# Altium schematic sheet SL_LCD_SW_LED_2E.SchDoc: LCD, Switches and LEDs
size B; Organization: Altium Limited; Address1: L3, 12a Rodborough Rd; Address2: Frenchs Forest; Address3: NSW; Address4: Australia 2086; DocumentNumber: 3; SheetNumber: 3; SheetTotal: 5; Library Name: SpiritLevel_2E.SchLib
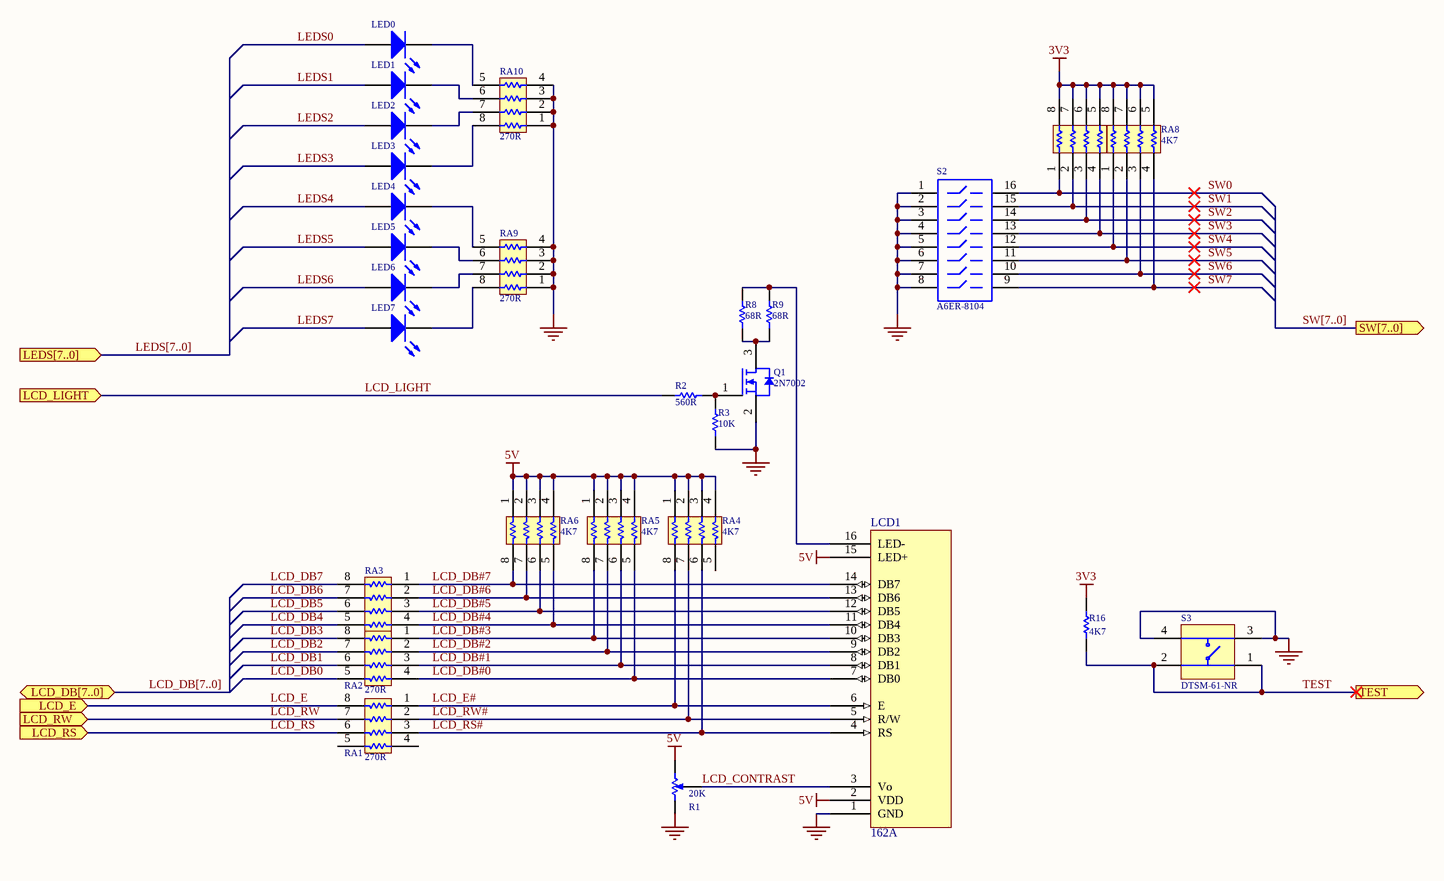
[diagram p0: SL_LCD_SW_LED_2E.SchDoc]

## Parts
LCD1  162A  [162A]
LED0  HSMH-C170  [SMD _LED]  (value not drawn)
LED1  HSMH-C170  [SMD _LED]  (value not drawn)
LED2  HSMH-C170  [SMD _LED]  (value not drawn)
LED3  HSMH-C170  [SMD _LED]  (value not drawn)
LED4  HSMH-C170  [SMD _LED]  (value not drawn)
LED5  HSMH-C170  [SMD _LED]  (value not drawn)
LED6  HSMH-C170  [SMD _LED]  (value not drawn)
LED7  HSMH-C170  [SMD _LED]  (value not drawn)
Q1  2N7002  [SO-G3]
R1  20K  [POT4MM-2]
R2  560R  [CC2012-0805]
R3  10K  [CC2012-0805]
R8  68R  [CC2012-0805]
R9  68R  [CC2012-0805]
R16  4K7  [CC2012-0805]
RA1  270R  [MNR34]
RA2  270R  [MNR34]
RA3  270R  [MNR34]
RA4  4K7  [MNR34T]
RA5  4K7  [MNR34T]
RA6  4K7  [MNR34T]
RA7  4K7  [MNR34T]
RA8  4K7  [MNR34T]
RA9  270R  [MNR34T]
RA10  270R  [MNR34T]
S2  A6ER-8104  [DIP-16-KEY]
S3  DTSM-61-NR  [B3FS_SWITCH]

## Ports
LCD_DB[7..0] (bidir), LCD_E (in), LCD_LIGHT (in), LCD_RS (in), LCD_RW (in), LEDS[7..0] (in), SW[7..0] (out), TEST (out)

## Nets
3V3: R16.1 RA7.5 RA7.6 RA7.7 RA7.8 RA8.5 RA8.6 RA8.7 RA8.8
5V: LCD1.2(VDD) LCD1.15(LED+) R1.CW(+) RA4.1 RA4.2 RA4.3 RA4.4 RA5.1 RA5.2 RA5.3 RA5.4 RA6.1 RA6.2 RA6.3 RA6.4
GND: LCD1.1(GND) Q1.2 R1.CCW(-) R3.1 RA9.1 RA9.2 RA9.3 RA9.4 RA10.1 RA10.2 RA10.3 RA10.4 S2.1 S2.2 S2.3 S2.4 S2.5 S2.6 S2.7 S2.8 S3.3 S3.4
LCD_CONTRAST: LCD1.3(Vo) R1.W
LCD_DB0: RA2.5
LCD_DB1: RA2.6
LCD_DB2: RA2.7
LCD_DB3: RA2.8
LCD_DB4: RA3.5
LCD_DB5: RA3.6
LCD_DB6: RA3.7
LCD_DB7: RA3.8
LCD_DB#0: LCD1.7(DB0) RA2.4 RA5.5
LCD_DB#1: LCD1.8(DB1) RA2.3 RA5.6
LCD_DB#2: LCD1.9(DB2) RA2.2 RA5.7
LCD_DB#3: LCD1.10(DB3) RA2.1 RA5.8
LCD_DB#4: LCD1.11(DB4) RA3.4 RA6.5
LCD_DB#5: LCD1.12(DB5) RA3.3 RA6.6
LCD_DB#6: LCD1.13(DB6) RA3.2 RA6.7
LCD_DB#7: LCD1.14(DB7) RA3.1 RA6.8
LCD_E: RA1.8 ; port LCD_E
LCD_E#: LCD1.6(E) RA1.1 RA4.8
LCD_LIGHT: R2.1 ; port LCD_LIGHT
LCD_RS: RA1.6 ; port LCD_RS
LCD_RS#: LCD1.4(RS) RA1.3 RA4.6
LCD_RW: RA1.7 ; port LCD_RW
LCD_RW#: LCD1.5(R/W) RA1.2 RA4.7
LEDS0: LED0.1(A)
LEDS1: LED1.1(A)
LEDS2: LED2.1(A)
LEDS3: LED3.1(A)
LEDS4: LED4.1(A)
LEDS5: LED5.1(A)
LEDS6: LED6.1(A)
LEDS7: LED7.1(A)
SW0: RA7.1 S2.16
SW1: RA7.2 S2.15
SW2: RA7.3 S2.14
SW3: RA7.4 S2.13
SW4: RA8.1 S2.12
SW5: RA8.2 S2.11
SW6: RA8.3 S2.10
SW7: RA8.4 S2.9
TEST: R16.2 S3.1 S3.2 ; port TEST
NetLCD1_16: LCD1.16(LED-) R8.1 R9.1
NetLED0_2: LED0.2(K) RA10.5
NetLED1_2: LED1.2(K) RA10.6
NetLED2_2: LED2.2(K) RA10.7
NetLED3_2: LED3.2(K) RA10.8
NetLED4_2: LED4.2(K) RA9.5
NetLED5_2: LED5.2(K) RA9.6
NetLED6_2: LED6.2(K) RA9.7
NetLED7_2: LED7.2(K) RA9.8
NetQ1_1: Q1.1 R2.2 R3.2
NetQ1_3: Q1.3 R8.2 R9.2

Not connected (* = marked no-connect by the designer): RA1 4 5; RA4 5

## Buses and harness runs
bus LCD_DB[7..0] = port LCD_DB[7..0]
bus LEDS[7..0] = port LEDS[7..0]
bus SW[7..0] = port SW[7..0]

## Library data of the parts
LCD1 = 162A: 16 char * 2 line LCD character display with b/light
LED0-LED7 = HSMX-C670: Typical RED GaAs SMD LED Agilent make; AEMS Code: 2610081
Q1 = 2N7002: N Channel Mosfet
R1 = RPot SM: Square Trimming Potentiometer; AEMS Code: 1400226
R2 = RES: Resistor; AEMS Code: 1200723
R3 = RES: Resistor; AEMS Code: 1200006JT
R8 R9 = RES: Resistor; AEMS Code: 1200821
R16 = RES: Resistor; AEMS Code: 1200226
RA1-RA3 RA9 RA10 = MNR34: 3216x4 Resistor Array; AEMS Code: 1310010
RA4-RA8 = MNR34: 3216x4 Resistor Array; AEMS Code: 1300330
S2 = A6ER-8104: DIP Switch Side actuator long liver Piano Key
S3 = B3FS: SPNA SMD Keyboard Switch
